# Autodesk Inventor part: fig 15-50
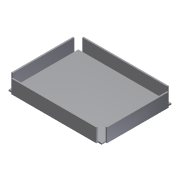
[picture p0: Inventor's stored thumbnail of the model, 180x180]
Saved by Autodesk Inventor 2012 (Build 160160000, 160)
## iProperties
Shininess: 77.0
Angle Display Precision: 2
Document Length Units: 11269
Document Angle Units: 11279
Document Time Units: 11290
Document Mass Units: 11283
Document Length Units Precision: 3
Document Angle Units Precision: 2
Compacted: True
Created: 2002-04
Part Number: fig 15-50
Document SubType Name: Sheet Metal
Density: 1 g/cm^3
Sheet Metal Rule: Default
Material: Default
Density: 0.0
Volumn: 0.0
Area: 0.0
PropertySet Name: Model Information
Control State: 0
Master: False
Checked Out: False
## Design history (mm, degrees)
sketch "Sketch1"
  geometry: L1 (-34, 28)-(36, 28); L2 (36, 28)-(36, -24.941); L3 (36, -24.941)-(-34, -24.941); L4 (-34, -24.941)-(-34, 28)
  constraints: 8 end point, 2 parallel, 1 horizontal, 1 perpendicular
extrude "Extrusion1" join sketch "Sketch1" distance "d0" = 10; taper "d1" = 0 deg
shell "Shell1" dims "d2" = 1
feature "Corner9" dims "d27" = 4 (= CornerReliefSize), "d28" = 1 (= BendRadius), "d29" = 3, "d30" = 0, "d31" = 10, "Thickness" = 1
feature "Corner10" dims "d32" = 4 (= CornerReliefSize), "d33" = 1 (= BendRadius), "d34" = 3, "d35" = 0, "d36" = 10, "Thickness" = 1
body "Solid1"
other parameters: "BendRadius" = 1 (= Thickness), "BendReliefWidth" = 1 (= Thickness), "BendReliefDepth" = 0.5 (= 0.5 x Thickness), "CornerReliefSize" = 4 (= 4 x Thickness), "SeamGap" = 0.01, "MinimumRemnant" = 2 (= 2 x Thickness), "TransitionRadius" = 1 (= BendRadius), "JacobiRadiusSize" = 1 (= Thickness), "GapSize" = 1 (= Thickness)
